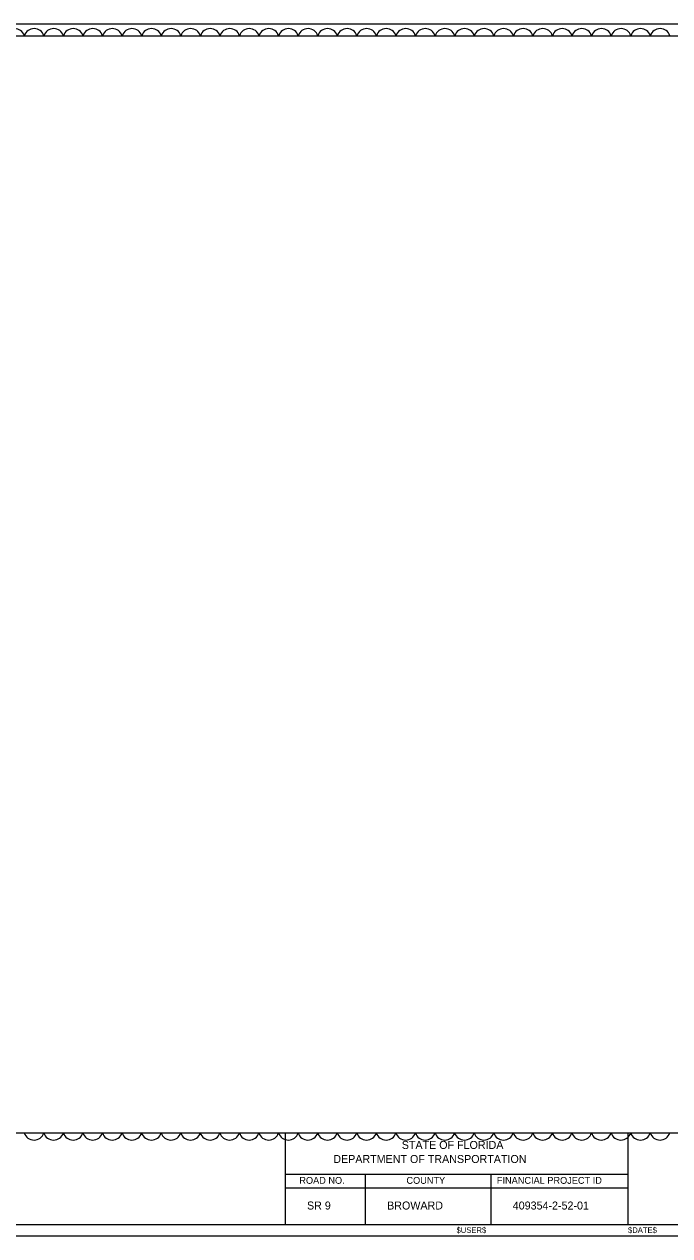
# Model space of a CAD drawing. Extents: x -811.3 to -790.1, y -2211.9 to -2188.9.
# Drawn here: x -804.97 to -799.32, y -2199.5 to -2188.9 of the extents above; entities that cross this region are included whole.
import ezdxf

# ---------------------------------------------------------------- set-up
doc = ezdxf.new("R2010")
doc.units = 0
for name, color, linetype in [('Cloud_dp', 7, 'Continuous'), ('PlotBorder_dp', 7, 'Continuous'), ('SheetBorder_dp', 7, 'Continuous'), ('SheetLines_dp', 7, 'Continuous'), ('TextMinor', 7, 'Continuous'), ('TextMisc', 7, 'Continuous')]:
    doc.layers.add(name, color=color, linetype=linetype)

msp = doc.modelspace()

# ---------------------------------------------------------------- linework, layer by layer
at = {"layer": 'Cloud_dp'}
for centre, start, end in [((-805.053, -2189.028), 17.5, 162.5), ((-804.882, -2189.028), 17.5, 162.5), ((-804.711, -2189.028), 17.5, 162.5), ((-804.54, -2189.028), 17.5, 162.5), ((-804.369, -2189.028), 17.5, 162.5), ((-804.198, -2189.028), 17.5, 162.5), ((-804.026, -2189.028), 17.5, 162.5), ((-803.855, -2189.028), 17.5, 162.5), ((-803.684, -2189.028), 17.5, 162.5), ((-803.513, -2189.028), 17.5, 162.5), ((-803.342, -2189.028), 17.5, 162.5), ((-803.171, -2189.028), 17.5, 162.5), ((-803, -2189.028), 17.5, 162.5), ((-802.829, -2189.028), 17.5, 162.5), ((-802.657, -2189.028), 17.5, 162.5), ((-802.486, -2189.028), 17.5, 162.5), ((-802.315, -2189.028), 17.5, 162.5), ((-802.144, -2189.028), 17.5, 162.5), ((-801.973, -2189.028), 17.5, 162.5), ((-801.802, -2189.028), 17.5, 162.5), ((-801.631, -2189.028), 17.5, 162.5), ((-801.46, -2189.028), 17.5, 162.5), ((-801.288, -2189.028), 17.5, 162.5), ((-801.117, -2189.028), 17.5, 162.5), ((-800.946, -2189.028), 17.5, 162.5), ((-800.775, -2189.028), 17.5, 162.5), ((-800.604, -2189.028), 17.5, 162.5), ((-800.433, -2189.028), 17.5, 162.5), ((-800.262, -2189.028), 17.5, 162.5), ((-800.091, -2189.028), 17.5, 162.5), ((-799.919, -2189.028), 17.5, 162.5), ((-799.748, -2189.028), 17.5, 162.5), ((-799.577, -2189.028), 17.5, 162.5), ((-799.406, -2189.028), 17.5, 162.5), ((-804.883, -2198.574), 197.5, 342.5), ((-804.712, -2198.574), 197.5, 342.5), ((-804.541, -2198.574), 197.5, 342.5), ((-804.37, -2198.574), 197.5, 342.5), ((-804.199, -2198.574), 197.5, 342.5), ((-804.027, -2198.574), 197.5, 342.5), ((-803.856, -2198.574), 197.5, 342.5), ((-803.685, -2198.574), 197.5, 342.5), ((-803.514, -2198.574), 197.5, 342.5), ((-803.343, -2198.574), 197.5, 342.5), ((-803.172, -2198.574), 197.5, 342.5), ((-803.001, -2198.574), 197.5, 342.5), ((-802.83, -2198.574), 197.5, 342.5), ((-802.658, -2198.574), 197.5, 342.5), ((-802.487, -2198.574), 197.5, 342.5), ((-802.316, -2198.574), 197.5, 342.5), ((-802.145, -2198.574), 197.5, 342.5), ((-801.974, -2198.574), 197.5, 342.5), ((-801.803, -2198.574), 197.5, 342.5), ((-801.632, -2198.574), 197.5, 342.5), ((-801.461, -2198.574), 197.5, 342.5), ((-801.289, -2198.574), 197.5, 342.5), ((-801.118, -2198.574), 197.5, 342.5), ((-800.947, -2198.574), 197.5, 342.5), ((-800.776, -2198.574), 197.5, 342.5), ((-800.605, -2198.574), 197.5, 342.5), ((-800.434, -2198.574), 197.5, 342.5), ((-800.263, -2198.574), 197.5, 342.5), ((-800.092, -2198.574), 197.5, 342.5), ((-799.921, -2198.574), 197.5, 342.5), ((-799.749, -2198.574), 197.5, 342.5), ((-799.578, -2198.574), 197.5, 342.5), ((-799.407, -2198.574), 197.5, 342.5)]:
    msp.add_arc(centre, 0.0897, start, end, dxfattribs=at)
at = {"layer": 'PlotBorder_dp'}
msp.add_lwpolyline([(-811.336, -2199.501), (-794.836, -2199.501), (-794.836, -2188.901), (-811.336, -2188.901)], close=True, dxfattribs=at)
at = {"layer": 'SheetBorder_dp'}
for p, q in [((-810.786, -2189.001), (-795.386, -2189.001)), ((-810.786, -2198.601), (-795.386, -2198.601)), ((-810.786, -2199.401), (-795.386, -2199.401))]:
    msp.add_line(p, q, dxfattribs=at)
at = {"layer": 'SheetLines_dp'}
for p, q in [((-802.686, -2198.601), (-802.686, -2199.401)), ((-799.686, -2199.401), (-799.686, -2198.601)), ((-802.686, -2198.961), (-799.686, -2198.961)), ((-801.986, -2198.961), (-801.986, -2199.401)), ((-800.886, -2198.961), (-800.886, -2199.401)), ((-802.686, -2199.081), (-799.686, -2199.081))]:
    msp.add_line(p, q, dxfattribs=at)

# ---------------------------------------------------------------- texts
at = {"layer": 'TextMinor'}
msp.add_text('$USER$', height=0.05, dxfattribs=at).set_placement((-801.187, -2199.476))
msp.add_text('$DATE$', height=0.05, rotation=360, dxfattribs=at).set_placement((-799.687, -2199.476))
at = {"layer": 'TextMisc'}
for s, height, p in [('STATE OF FLORIDA', 0.07, (-801.666, -2198.741)), ('DEPARTMENT OF TRANSPORTATION', 0.07, (-802.265, -2198.864)), ('ROAD NO.', 0.06, (-802.562, -2199.046)), ('COUNTY', 0.06, (-801.625, -2199.046)), ('FINANCIAL PROJECT ID', 0.06, (-800.834, -2199.046)), (' SR 9  ', 0.07, (-802.521, -2199.271)), ('  BROWARD   ', 0.07, (-801.846, -2199.271)), ('409354-2-52-01', 0.07, (-800.695, -2199.271))]:
    msp.add_text(s, height=height, dxfattribs=at).set_placement(p)

doc.saveas('drawing.dxf')
